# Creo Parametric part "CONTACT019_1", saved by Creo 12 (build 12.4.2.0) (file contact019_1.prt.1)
Units: Custom; MM, KILOGRAM, SECS

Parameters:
  PTC_WM_ITERATION = "0"
  PTC_WM_VERSION = "-.0"
  PTC_WM_LIFECYCLE_STATE = "In Work"
  PTC_WM_LIFECYCLE = "MO_CADDocument"
  PTC_WM_CREATED_BY = "Maximilian Roepper (Z0017RMS: MO)"
  PTC_WM_CREATED_ON = "18-Sep-26 11:36:42 AM"
  PTC_WM_MODIFIED_BY = "Maximilian Roepper (Z0017RMS: MO)"
  PTC_WM_MODIFIED_ON = "18-Sep-26 11:36:46 AM"
  PDMLINKNUMBER = "PDM000071455252"
  PTC_WM_NAME = "contact019_1.prt"
  PTC_WM_NUMBER = "PDM000071455252"

Other parameters: WEIGHT, WEIGHT_FACTOR, WEIGHT_ADD, _MASS_TEMP, _DIFF_TEMP, MC_ERRORS, SUPPLIER

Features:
  1. coordinate system
  2. datum plane "PRT_YZ"
  3. datum plane "PRT_XY"
  4. datum plane "PRT_XZ"
  5. coordinate system
  6. datum axis
  7. datum axis
  8. datum axis
  9. coordinate system
  10. imported feature

Other named items: PRT, SIEMENS_MO, DRW_VIEW_ORG, PRT_X, PRT_Y, PRT_Z, CS0, ROUGH_GROB

Layers: 00_STD_CSYS-KSYS, 01_STD_PLANES-EBENEN, 02_STD_AXES-ACHSEN, 03_STD_CSYS-KSYS, 24_IMPORT_FEAT-IMPORT_KE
